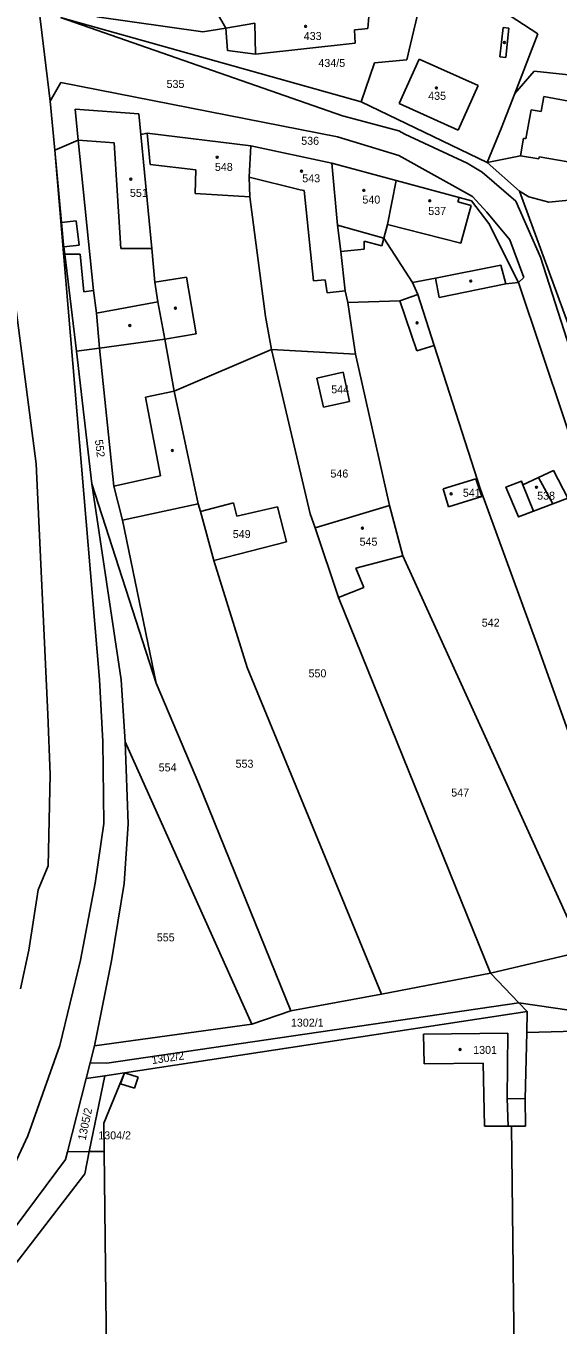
# Model space of a CAD drawing. Extents: x -563148 to -561712, y -1182311 to -1179502.
# Drawn here: x -562430.6 to -562330.8, y -1181019.2 to -1180775.6 of the extents above; entities that cross this region are included whole.
import ezdxf

# ---------------------------------------------------------------- set-up
doc = ezdxf.new("R2010")
doc.units = 0
for name, color, linetype in [('Vrstva 55', 7, 'Continuous'), ('Vrstva 56', 7, 'Continuous'), ('Vrstva 57', 7, 'Continuous')]:
    doc.layers.add(name, color=color, linetype=linetype)

msp = doc.modelspace()

# ---------------------------------------------------------------- linework, layer by layer
at = {"layer": 'Vrstva 55'}
for p, q in [((-562356.66, -1180762.53), (-562334.62, -1180777.08)), ((-562428.87, -1180766.18), (-562426.05, -1180789.71)), ((-562396.89, -1180769.35), (-562393.07, -1180776.06)), ((-562366.19, -1180772.32), (-562366.51, -1180776.11)), ((-562356.83, -1180772.25), (-562358.46, -1180779.03)), ((-562367.7, -1180789.85), (-562424.11, -1180774.04)), ((-562397.44, -1180776.71), (-562417.28, -1180773.93)), ((-562393.07, -1180776.06), (-562397.44, -1180776.71)), ((-562387.65, -1180775.07), (-562393.07, -1180776.06)), ((-562392.79, -1180780.23), (-562393.07, -1180776.06)), ((-562367.63, -1180776.23), (-562369.01, -1180776.37)), ((-562369.01, -1180776.37), (-562368.84, -1180778.83)), ((-562366.51, -1180776.11), (-562367.63, -1180776.23)), ((-562334.62, -1180777.08), (-562338.95, -1180788.27)), ((-562368.84, -1180778.83), (-562387.56, -1180780.89)), ((-562358.46, -1180779.03), (-562359.16, -1180781.95)), ((-562387.56, -1180780.89), (-562392.79, -1180780.23)), ((-562359.16, -1180781.95), (-562365.23, -1180782.51)), ((-562365.23, -1180782.51), (-562367.7, -1180789.85)), ((-562338.95, -1180788.27), (-562335.3, -1180784.09)), ((-562335.3, -1180784.09), (-562326.48, -1180785.04)), ((-562424.04, -1180786.23), (-562426.05, -1180789.71)), ((-562372.19, -1180796.42), (-562424.04, -1180786.23)), ((-562338.95, -1180788.27), (-562341.5, -1180794.86)), ((-562426.05, -1180789.71), (-562425.15, -1180798.89)), ((-562421.34, -1180791.25), (-562420.81, -1180797.06)), ((-562409.43, -1180792.11), (-562421.34, -1180791.25)), ((-562344.08, -1180801.2), (-562367.7, -1180789.85)), ((-562409.05, -1180795.95), (-562409.43, -1180792.11)), ((-562407.83, -1180795.73), (-562409.05, -1180795.95)), ((-562407, -1180817.34), (-562409.05, -1180795.95)), ((-562388.44, -1180798.08), (-562407.83, -1180795.73)), ((-562360.68, -1180799.93), (-562372.19, -1180796.42)), ((-562341.5, -1180794.86), (-562344.08, -1180801.2)), ((-562420.81, -1180797.06), (-562425.15, -1180798.89)), ((-562425.15, -1180798.89), (-562423.88, -1180812.49)), ((-562417.89, -1180825.21), (-562420.81, -1180797.06)), ((-562388.75, -1180803.97), (-562388.44, -1180798.08)), ((-562373.21, -1180801.33), (-562388.44, -1180798.08)), ((-562361.16, -1180804.61), (-562373.21, -1180801.33)), ((-562372.14, -1180812.98), (-562373.21, -1180801.33)), ((-562346.87, -1180807.58), (-562360.68, -1180799.93)), ((-562337.87, -1180799.94), (-562344.08, -1180801.2)), ((-562338.03, -1180806.59), (-562344.08, -1180801.2)), ((-562334.44, -1180800.54), (-562337.87, -1180799.94)), ((-562334.35, -1180800.16), (-562334.44, -1180800.54)), ((-562325.68, -1180801.66), (-562334.35, -1180800.16)), ((-562388.58, -1180807.65), (-562388.75, -1180803.97)), ((-562362.78, -1180812.86), (-562361.16, -1180804.61)), ((-562349.38, -1180807.79), (-562361.16, -1180804.61)), ((-562385.65, -1180830.09), (-562388.58, -1180807.65)), ((-562347.07, -1180808.41), (-562349.38, -1180807.79)), ((-562343.8, -1180812.68), (-562347.07, -1180808.41)), ((-562344.17, -1180810.55), (-562346.87, -1180807.58)), ((-562336.29, -1180807.67), (-562338.03, -1180806.59)), ((-562324.09, -1180844.8), (-562338.03, -1180806.59)), ((-562332.52, -1180808.66), (-562336.29, -1180807.67)), ((-562326.89, -1180808.08), (-562332.52, -1180808.66)), ((-562339.87, -1180815.72), (-562344.17, -1180810.55)), ((-562423.88, -1180812.49), (-562423.53, -1180816.67)), ((-562371.57, -1180817.92), (-562372.14, -1180812.98)), ((-562363.48, -1180815.38), (-562362.78, -1180812.86)), ((-562338.22, -1180823.73), (-562343.8, -1180812.68)), ((-562358.09, -1180823.72), (-562363.48, -1180815.38)), ((-562337.21, -1180822.8), (-562339.87, -1180815.72)), ((-562423.53, -1180816.67), (-562423.49, -1180817.02)), ((-562423.49, -1180817.02), (-562423.31, -1180818.43)), ((-562423.31, -1180818.43), (-562421.09, -1180836.6)), ((-562406.39, -1180823.66), (-562407, -1180817.34)), ((-562370.73, -1180825.27), (-562371.57, -1180817.92)), ((-562353.79, -1180822.88), (-562358.09, -1180823.72)), ((-562353.1, -1180826.52), (-562353.79, -1180822.88)), ((-562338.22, -1180823.73), (-562337.21, -1180822.8)), ((-562417.36, -1180829.45), (-562417.89, -1180825.21)), ((-562405.87, -1180827.33), (-562406.39, -1180823.66)), ((-562370.22, -1180827.49), (-562370.73, -1180825.27)), ((-562357.12, -1180825.97), (-562358.09, -1180823.72)), ((-562354.06, -1180835.54), (-562357.12, -1180825.97)), ((-562340.62, -1180823.94), (-562353.1, -1180826.52)), ((-562338.22, -1180823.73), (-562340.62, -1180823.94)), ((-562321.99, -1180872.35), (-562338.22, -1180823.73)), ((-562404.55, -1180834.36), (-562405.87, -1180827.33)), ((-562360.49, -1180827.16), (-562370.22, -1180827.49)), ((-562369.3, -1180833.86), (-562370.22, -1180827.49)), ((-562357.3, -1180836.55), (-562360.49, -1180827.16)), ((-562416.76, -1180836.01), (-562417.36, -1180829.45)), ((-562384.57, -1180836.26), (-562385.65, -1180830.09)), ((-562402.78, -1180844.07), (-562404.55, -1180834.36)), ((-562368.82, -1180837.13), (-562369.3, -1180833.86)), ((-562354.06, -1180835.54), (-562357.3, -1180836.55)), ((-562345.36, -1180862.51), (-562354.06, -1180835.54)), ((-562421.09, -1180836.6), (-562418.2, -1180861.47)), ((-562414.07, -1180861.92), (-562416.76, -1180836.01)), ((-562384.57, -1180836.26), (-562402.78, -1180844.07)), ((-562368.82, -1180837.13), (-562384.57, -1180836.26)), ((-562377.27, -1180867.05), (-562384.57, -1180836.26)), ((-562362.42, -1180865.49), (-562368.82, -1180837.13)), ((-562376.02, -1180841.62), (-562371.08, -1180840.54)), ((-562371.08, -1180840.54), (-562369.89, -1180846)), ((-562374.82, -1180847.07), (-562376.02, -1180841.62)), ((-562398.3, -1180865.21), (-562402.78, -1180844.07)), ((-562369.89, -1180846), (-562374.82, -1180847.07)), ((-562418.2, -1180861.47), (-562412.73, -1180898.21)), ((-562406.18, -1180898.8), (-562418.2, -1180861.47)), ((-562412.47, -1180868.27), (-562414.07, -1180861.92)), ((-562352.38, -1180862.41), (-562346.22, -1180860.52)), ((-562351.33, -1180865.78), (-562352.38, -1180862.41)), ((-562346.22, -1180860.52), (-562345.11, -1180863.84)), ((-562334.78, -1180891.43), (-562345.36, -1180862.51)), ((-562337.4, -1180861.65), (-562334.5, -1180860.3)), ((-562345.11, -1180863.84), (-562351.33, -1180865.78)), ((-562398.3, -1180865.21), (-562412.47, -1180868.27)), ((-562397.83, -1180866.66), (-562398.3, -1180865.21)), ((-562397.83, -1180866.66), (-562391.65, -1180864.99)), ((-562395.35, -1180875.81), (-562397.83, -1180866.66)), ((-562391.65, -1180864.99), (-562391.01, -1180867.49)), ((-562391.01, -1180867.49), (-562383.41, -1180865.74)), ((-562383.41, -1180865.74), (-562381.72, -1180872.3)), ((-562376.37, -1180869.71), (-562377.27, -1180867.05)), ((-562376.37, -1180869.71), (-562362.42, -1180865.49)), ((-562359.95, -1180874.95), (-562362.42, -1180865.49)), ((-562331.78, -1180865.22), (-562335.4, -1180866.59)), ((-562412.47, -1180868.27), (-562406.18, -1180898.8)), ((-562371.96, -1180882.78), (-562376.37, -1180869.71)), ((-562381.72, -1180872.3), (-562395.35, -1180875.81)), ((-562389.11, -1180895.91), (-562395.35, -1180875.81)), ((-562359.95, -1180874.95), (-562368.74, -1180877.24)), ((-562341.92, -1180914.43), (-562359.95, -1180874.95)), ((-562368.74, -1180877.24), (-562367.21, -1180880.89)), ((-562367.21, -1180880.89), (-562371.96, -1180882.78)), ((-562343.47, -1180953.2), (-562371.96, -1180882.78)), ((-562315.24, -1180946.38), (-562334.78, -1180891.43)), ((-562363.9, -1180957.15), (-562389.11, -1180895.91)), ((-562412.73, -1180898.21), (-562411.99, -1180909.84)), ((-562398.18, -1180917.7), (-562406.18, -1180898.8)), ((-562411.99, -1180909.84), (-562411.41, -1180925.22)), ((-562388.21, -1180962.78), (-562411.99, -1180909.84)), ((-562327.75, -1180945.69), (-562341.92, -1180914.43)), ((-562380.91, -1180960.28), (-562398.18, -1180917.7)), ((-562411.41, -1180925.22), (-562412.16, -1180936.37)), ((-562412.16, -1180936.37), (-562414.52, -1180950.86)), ((-562326.01, -1180949.08), (-562343.47, -1180953.2)), ((-562414.52, -1180950.86), (-562417.69, -1180966.83)), ((-562343.47, -1180953.2), (-562363.9, -1180957.15)), ((-562338.16, -1180958.73), (-562343.47, -1180953.2)), ((-562363.9, -1180957.15), (-562380.91, -1180960.28)), ((-562415.43, -1180970.08), (-562338.16, -1180958.73)), ((-562336.59, -1180960.36), (-562338.16, -1180958.73)), ((-562338.16, -1180958.73), (-562302.33, -1180963.96)), ((-562336.59, -1180960.36), (-562412.11, -1180971.86)), ((-562380.91, -1180960.28), (-562388.21, -1180962.78)), ((-562336.69, -1180964.31), (-562336.59, -1180960.36)), ((-562388.21, -1180962.78), (-562417.69, -1180966.83)), ((-562356.02, -1180964.63), (-562340.22, -1180964.41)), ((-562355.95, -1180970.21), (-562356.02, -1180964.63)), ((-562340.22, -1180964.41), (-562340.34, -1180976.69)), ((-562336.69, -1180964.31), (-562336.99, -1180976.75)), ((-562319.38, -1180963.8), (-562336.69, -1180964.31)), ((-562417.69, -1180966.83), (-562418.51, -1180970.01)), ((-562418.51, -1180970.01), (-562419.26, -1180972.95)), ((-562418.51, -1180970.01), (-562415.43, -1180970.08)), ((-562415.96, -1180981.34), (-562412.11, -1180971.86)), ((-562412.11, -1180971.86), (-562415.8, -1180972.43)), ((-562344.89, -1180970.09), (-562355.95, -1180970.21)), ((-562344.58, -1180981.88), (-562344.89, -1180970.09)), ((-562419.26, -1180972.95), (-562422.79, -1180986.68)), ((-562415.8, -1180972.43), (-562419.26, -1180972.95)), ((-562418.69, -1180986.63), (-562415.8, -1180972.43)), ((-562340.34, -1180976.69), (-562336.99, -1180976.75)), ((-562336.99, -1180976.75), (-562336.95, -1180981.86)), ((-562415.9, -1180986.6), (-562415.96, -1180981.34)), ((-562340.16, -1180981.87), (-562344.58, -1180981.88)), ((-562339.56, -1180981.87), (-562340.16, -1180981.87)), ((-562336.95, -1180981.86), (-562339.56, -1180981.87)), ((-562339.56, -1180981.87), (-562338.26, -1181097.09)), ((-562422.79, -1180986.68), (-562423.16, -1180988.12)), ((-562422.79, -1180986.68), (-562418.69, -1180986.63)), ((-562419.54, -1180990.82), (-562418.69, -1180986.63)), ((-562418.69, -1180986.63), (-562415.9, -1180986.6)), ((-562414.69, -1181094.34), (-562415.9, -1180986.6)), ((-562423.16, -1180988.12), (-562442.47, -1181013.99)), ((-562439.5, -1181016.71), (-562419.54, -1180990.82))]:
    msp.add_line(p, q, dxfattribs=at)
for points in [[(-562334.5, -1180860.3), (-562331.68, -1180858.98), (-562328.96, -1180864.16), (-562331.78, -1180865.22)], [(-562335.4, -1180866.59), (-562338.25, -1180867.67), (-562340.6, -1180862.08), (-562337.69, -1180860.93), (-562337.4, -1180861.65)]]:
    msp.add_lwpolyline(points, dxfattribs=at)
at = {"layer": 'Vrstva 56'}
for p, q in [((-562371.22, -1180792.45), (-562424.11, -1180774.04)), ((-562387.56, -1180780.89), (-562387.65, -1180775.07)), ((-562341.71, -1180781.4), (-562341.13, -1180775.94)), ((-562341.13, -1180775.94), (-562340.04, -1180776.06)), ((-562340.04, -1180776.06), (-562340.62, -1180781.52)), ((-562356.87, -1180781.83), (-562360.6, -1180790.15)), ((-562345.81, -1180786.81), (-562356.87, -1180781.83)), ((-562340.62, -1180781.52), (-562341.71, -1180781.4)), ((-562349.53, -1180795.15), (-562345.81, -1180786.81)), ((-562333.96, -1180791.68), (-562333.47, -1180788.87)), ((-562333.47, -1180788.87), (-562327.82, -1180789.89)), ((-562349.53, -1180795.15), (-562360.6, -1180790.15)), ((-562336.84, -1180796.75), (-562335.88, -1180791.34)), ((-562335.88, -1180791.34), (-562333.96, -1180791.68)), ((-562360.67, -1180795.26), (-562371.22, -1180792.45)), ((-562407.28, -1180801.58), (-562407.83, -1180795.73)), ((-562359.54, -1180795.88), (-562360.67, -1180795.26)), ((-562347.83, -1180801.32), (-562359.54, -1180795.88)), ((-562337.87, -1180799.94), (-562337.29, -1180796.67)), ((-562337.29, -1180796.67), (-562336.84, -1180796.75)), ((-562416.79, -1180898.16), (-562425.15, -1180798.89)), ((-562414.03, -1180797.53), (-562420.81, -1180797.06)), ((-562412.77, -1180817.33), (-562414.03, -1180797.53)), ((-562398.74, -1180802.62), (-562407.28, -1180801.58)), ((-562345.02, -1180803.03), (-562347.83, -1180801.32)), ((-562398.83, -1180807.02), (-562398.74, -1180802.62)), ((-562379.14, -1180806.32), (-562388.75, -1180803.97)), ((-562338.73, -1180808.44), (-562345.02, -1180803.03)), ((-562378.43, -1180806.49), (-562379.14, -1180806.32)), ((-562376.64, -1180823.42), (-562378.43, -1180806.49)), ((-562388.58, -1180807.65), (-562398.83, -1180807.02)), ((-562349.38, -1180807.79), (-562349.6, -1180808.57)), ((-562349.6, -1180808.57), (-562347.12, -1180809.27)), ((-562334.09, -1180818.96), (-562338.73, -1180808.44)), ((-562347.12, -1180809.27), (-562349.05, -1180816.34)), ((-562423.88, -1180812.49), (-562421.15, -1180812.17)), ((-562421.15, -1180812.17), (-562420.62, -1180816.71)), ((-562363.48, -1180815.38), (-562372.14, -1180812.98)), ((-562349.05, -1180816.34), (-562362.78, -1180812.86)), ((-562367.15, -1180815.96), (-562367.16, -1180817.44)), ((-562363.88, -1180816.83), (-562367.15, -1180815.96)), ((-562363.48, -1180815.38), (-562363.88, -1180816.83)), ((-562420.62, -1180816.71), (-562423.49, -1180817.02)), ((-562423.31, -1180818.43), (-562420.43, -1180818.43)), ((-562420.43, -1180818.43), (-562419.74, -1180825.44)), ((-562407, -1180817.34), (-562412.77, -1180817.33)), ((-562367.16, -1180817.44), (-562371.57, -1180817.92)), ((-562428.64, -1180857.69), (-562433.57, -1180819.74)), ((-562353.79, -1180822.88), (-562341.54, -1180820.46)), ((-562341.54, -1180820.46), (-562340.62, -1180823.94)), ((-562318.62, -1180867.4), (-562334.09, -1180818.96)), ((-562406.39, -1180823.66), (-562400.5, -1180822.74)), ((-562400.5, -1180822.74), (-562398.67, -1180833.32)), ((-562374.46, -1180823.19), (-562376.64, -1180823.42)), ((-562374.11, -1180825.65), (-562374.46, -1180823.19)), ((-562419.74, -1180825.44), (-562417.89, -1180825.21)), ((-562370.73, -1180825.27), (-562374.11, -1180825.65)), ((-562360.49, -1180827.16), (-562357.12, -1180825.97)), ((-562417.36, -1180829.45), (-562405.87, -1180827.33)), ((-562404.55, -1180834.36), (-562416.76, -1180836.01)), ((-562398.67, -1180833.32), (-562404.55, -1180834.36)), ((-562416.76, -1180836.01), (-562421.09, -1180836.6)), ((-562408.14, -1180845.21), (-562402.78, -1180844.07)), ((-562405.34, -1180859.95), (-562408.14, -1180845.21)), ((-562426.49, -1180904.68), (-562428.64, -1180857.69)), ((-562414.07, -1180861.92), (-562405.34, -1180859.95)), ((-562337.4, -1180861.65), (-562335.4, -1180866.59)), ((-562331.78, -1180865.22), (-562334.5, -1180860.3)), ((-562416.15, -1180909.78), (-562416.79, -1180898.16)), ((-562426.49, -1180904.68), (-562426.05, -1180915.95)), ((-562415.96, -1180925.15), (-562416.15, -1180909.78)), ((-562426.05, -1180915.95), (-562426.39, -1180933.07)), ((-562417.62, -1180936.3), (-562415.96, -1180925.15)), ((-562426.39, -1180933.07), (-562428.25, -1180937.55)), ((-562428.25, -1180937.55), (-562430.01, -1180948.89)), ((-562420.32, -1180950.78), (-562417.62, -1180936.3)), ((-562430.01, -1180948.89), (-562431.61, -1180956.13)), ((-562424.25, -1180966.74), (-562420.32, -1180950.78)), ((-562424.25, -1180966.74), (-562430.19, -1180983.7)), ((-562412.82, -1180973.91), (-562412.11, -1180971.86)), ((-562412.11, -1180971.86), (-562409.51, -1180972.69)), ((-562410.21, -1180974.78), (-562412.82, -1180973.91)), ((-562409.51, -1180972.69), (-562410.21, -1180974.78)), ((-562340.34, -1180976.69), (-562340.16, -1180981.87)), ((-562430.19, -1180983.7), (-562444, -1181013.04))]:
    msp.add_line(p, q, dxfattribs=at)
at = {"layer": 'Vrstva 57'}
for centre in [(-562378.14, -1180775.7), (-562340.87, -1180778.73), (-562353.63, -1180787.24), (-562394.71, -1180800.24), (-562378.9, -1180802.84), (-562410.92, -1180804.33), (-562367.23, -1180806.44), (-562354.88, -1180808.38), (-562347.2, -1180823.44), (-562402.56, -1180828.53), (-562411.1, -1180831.77), (-562357.26, -1180831.27), (-562403.13, -1180855.2), (-562334.87, -1180862.11), (-562350.86, -1180863.32), (-562367.51, -1180869.77), (-562349.2, -1180967.5)]:
    msp.add_circle(centre, 0.175, dxfattribs=at)

# ---------------------------------------------------------------- texts
for s, p in [('433', (-562378.5, -1180778.25)), ('434/5', (-562375.75, -1180783.31)), ('535', (-562404.21, -1180787.24)), ('435', (-562355.17, -1180789.47)), ('536', (-562378.97, -1180797.9)), ('548', (-562395.15, -1180802.8)), ('543', (-562378.77, -1180804.93)), ('551', (-562411.08, -1180807.66)), ('540', (-562367.5, -1180808.92)), ('537', (-562355.15, -1180811.05)), ('544', (-562373.34, -1180844.49)), ('546', (-562373.49, -1180860.28)), ('541', (-562348.67, -1180863.88)), ('549', (-562391.8, -1180871.62)), ('545', (-562368.03, -1180873.06)), ('542', (-562345.12, -1180888.23)), ('550', (-562377.6, -1180897.73)), ('553', (-562391.28, -1180914.68)), ('554', (-562405.69, -1180915.37)), ('547', (-562350.84, -1180920.08)), ('555', (-562406.04, -1180947.23)), ('1302/1', (-562380.9, -1180963.22)), ('1301', (-562346.73, -1180968.33)), ('1304/2', (-562417.01, -1180984.35))]:
    msp.add_text(s, height=1.5, dxfattribs=at).set_placement(p)
for s, rotation, p in [('552', 276.9833, (-562417.65, -1180853.25)), ('538', 0.0004, (-562334.74, -1180864.43)), ('1302/2', 8.3275, (-562406.9, -1180970.25)), ('1305/2', 78.1028, (-562419.4, -1180984.62))]:
    msp.add_text(s, height=1.5, rotation=rotation, dxfattribs=at).set_placement(p)

doc.saveas('drawing.dxf')
